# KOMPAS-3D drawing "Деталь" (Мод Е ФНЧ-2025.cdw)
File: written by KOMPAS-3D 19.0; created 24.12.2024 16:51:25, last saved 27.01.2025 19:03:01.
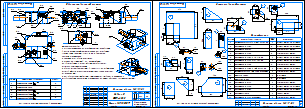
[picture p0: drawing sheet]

Sheets 1-2: A3, landscape

Document properties: Автор: WELDER_72; Масса: 1.76364; Форматы листов документа: 2xA3; Полное имя файла: Модули на РЧ\Модуль Е Степанов.m3d

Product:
- Part/product: Деталь
    Материал: Сталь 12Х18Н10Т ГОСТ 19277-2016 (density 7900 kg/m3)
    Масса: 1.76364
  - Body: Тело 29
      Масса: 0.05056
  - Body: Тело 1
      Масса: 0.763543
  - Body: Тело 2
      Масса: 0.0303024
  - Body: Тело 3
      Масса: 0.763543
  - Body: Тело 4
      Масса: 0.0497658
  - Body: Тело 5
      Масса: 0.074576
  - Body: Тело 8
      Масса: 0.0714775
  - Body: Тело 9
      Масса: 0.0714775
  - Body: Тело 10
      Масса: 0.0143451
  - Body: Тело 12
      Масса: 0.0148911
  - Body: Тело 14
      Масса: 0.0715026
  - Body: Тело 17
      Масса: 0.074576
  - Body: Тело 18
      Масса: 0.0277217
  - Body: Тело 19
      Масса: 0.193536
  - Body: Тело 20
      Масса: 0.763543
  - Body: Тело 21
      Масса: 0.088638
  - Body: Тело 22
      Масса: 0.763543
  - Body: Тело 23
      Масса: 0.041712
  - Body: Тело 24
      Масса: 0.041712
  - Body: Тело 25
      Масса: 0.0277217
  - Body: Тело 26
      Масса: 0.0555824

Title block, sheet 1: Наименование: Модуль Е / ФНЧ-2025; designation: Процесс сварки 141 (РАД); Материал: Сталь 12Х18Н10Т; Масса: 1,76; sheet number: 1; Количество листов документа: 2; organisation: Чемпионат ПМ / "Профессионалы"; Форматы листов документа: A3; stored path: C:\Users\WELDER_72\Desktop\Степан Курсовая НЕ УДАЛЯТЬ ДО СДАЧИ\Пробники на РЧ\Модуль Г Степан.cdw; Разработал: Степанов С.С.; Проверил: Калашников В.А.; Утвердил: Дюкова С. В.
Title block, sheet 2: sheet number: 2; stored path: C:\Users\Степан\Desktop\Модули на РЧ\Чертежи\Модуль Е Степанов.cdw

Views: Спереди 11, Спереди, Проекционный вид 12, Проекционный вид 13, Проекционный вид 14, Проекционный вид 16
Referenced files in C:\Users\WELDER_72\Desktop\Степан Курсовая НЕ УДАЛЯТЬ ДО СДАЧИ\Пробники на РЧ\: Модуль Е Степанов.m3d
Referenced files in C:\Users\Степан\Desktop\Модули на РЧ\: Модуль Е Степанов.m3d
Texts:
  Сборочно-сварочный чертеж
  Все расмеры на чертеже указаны в миллиметрах
  Технические условия:
  1. Сборку конструкции на прихваткиможно производить
  в любом пространственном положении. Все прихватки
  должны быть длиной не более 10 мм и выполнены
  снаружи конструкции.
  2. Очистка посе сварки запрещена.
  3. Каждую из деталей "9"," 10" - установить
  на две прихватки, а после завершения сварочного
  процесса аккуратно удалить.
  4. Сварка модуля выполняется в оин проход. за повторный
  прогрев шва без присадочного материала баллы за модуль
  не начисляются.
  5. Вся сварка осуществляется относительно основания - пластины "1".
  Переворачивать и наклонять конструкцию на этапе сварочных работ запрещается.
  № св. шва
  Стандарт и обозначения
  Кол-во
  ГОСТ 14771-76-Т1- 2 +1
  ГОСТ 14771-76-С2
  ГОСТ 14771-76-У4- 2
  ГОСТ 23518-79-Т5- 3 +1
  ГОСТ 23518-79-У2- 3 +1
  Деталировочный чертеж
  № дет.
  Наименование, размеры
  шт.
  Пластинна 2х180х190 с отв. 80х40 мм
  Сложная форма, см. чертеж
  Пластина 2х80х118
  Пластина 2х113х40
  Прямоугольная форма
  Пластина 2х80х33
  Пластина 2х40х118 с рад.  16 мм
  Пластина 2х40х78 с рад.  16 мм
  Пластина 2х40х44
  Пластина 2х80х155 с отв. 40х80 мм
  Пластина 2х40х80 с отв.  8 мм (заглушка)
  Труба  8х2-50
  См. чертеж
  Труба  38х2-40
  Пластина 2х85х66
  Пластина 2х80х85
  Пластина 2х92х148
  Пластина  34х2
  Пластина 2х40х80 (заглушка)
  Круглая форма
Dimensions and other numbers on the sheet: 4; 1; 3; 11; 12; 14; 5; 6; 7; 13; 85; 80; 2; 10; 30 2; 15; 33 2; 9; 190; 180; 25; 45; 40; 118; 113; 33; 16; 78; 38; 44; 155; 20; 8; 50; 34; 66; 92; 148; 97,4; 1:2; 1,76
